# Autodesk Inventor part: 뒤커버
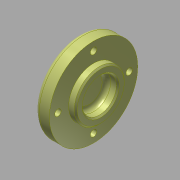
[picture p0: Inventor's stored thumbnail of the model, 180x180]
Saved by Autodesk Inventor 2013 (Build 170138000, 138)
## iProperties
Created: 2015-12
Part Number: 뒤커버
Document SubType Name: Modeling
Designer: mdu
Density: 2.71 g/cm^3
Material: 알루미늄 6061
Mass: 56.2007 g
Surface Area: 84.0408 cm^2
Volume: 20.7383 cm^3
Author: mdu
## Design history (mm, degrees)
sketch "스케치1"
  geometry: L1 (-7.5, 0)-(7.5, 0); L2 (-7.5, 0)-(-7.5, 31); L3 (-7.5, 31)-(2.5, 31); L4 (2.5, 31)-(2.5, 17.5); L5 (2.5, 17.5)-(7.5, 17.5); L6 (7.5, 17.5)-(7.5, 0); 2 further points
  constraints: 12 end point, 3 parallel, 1 coincident, 1 horizontal, 1 midpoint, 1 perpendicular
  dimensions: "d0" = 15 distance of L1.start L1.end; "d1" = 62 diameter of L3 L1; "d2" = 35 diameter of L5 L1; "d34" = 10 distance of L2.end L3.end
revolve "회전1" sketch "스케치1" stored, may be unused: angle "d6" = 90 deg
sketch "스케치2" dims "d32" = 50
  geometry: 3 further points
  constraints: 2 vertical alignment, 1 coincident, 2 other
hole "구멍1" sketch "스케치2" at (0, 25) diameter "d8" = 4.5; stored, may be unused: countersink angle "d12" = 90 deg, drill point angle "d14" = 118 deg; dims "d9" = 6, "d10" = 8, "d11" = 4.4, "d13" = 8
hole "구멍2" diameter "d20" = 24; stored, may be unused: countersink angle "d24" = 90 deg, drill point angle "d26" = 0 deg; dims "d18" = 10, "d19" = 10, "d21" = 6, "d22" = 8, "d23" = 4.4, "d25" = 8
fillet "모깎기1" dims "d27" = 3
fillet "모깎기2" dims "d28" = 3
chamfer "모따기1" distance "d29" = 1; stored, may be unused: second distance "d30" = 2, angle "d31" = 45 deg
node "솔리드1"
pattern_circular "원형 패턴1" dims angle "d16" = 360 deg
